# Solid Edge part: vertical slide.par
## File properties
Author: Deepak Maini
Template: Normal.par
Last saved by: Robert a Rhodes jr
Revision: 19
Application: Solid Edge
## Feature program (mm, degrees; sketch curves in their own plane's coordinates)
sketch for "unnamed Protrusion 1" plane through (0, 0, 0) normal (0, 0, 1) x-axis (1, 0, 0)
  line (-50, 27.936) -> (50, 27.936)
  line (50, 27.936) -> (50, -8.064)
  arc centre (0, 78.5385) radius 100 from (-50, -8.064) to (50, -8.064) ccw
  line (-50, 27.936) -> (-50, -8.064)
extrude "unnamed Protrusion 1" add finite 240 symmetric
sketch for "unnamed Cutout 1" plane through (0, 27.936, 0) normal (0, 1, 0) x-axis (-1, 0, 0)
  arc centre (0, 3) radius 123 from (-50, -109.3788) to (50, -109.3788) ccw
extrude "unnamed Cutout 1" cut through along -normal
sketch for "unnamed Protrusion 2" plane through (0, -30.264, 0) normal (0, 1, 0) x-axis (-1, 0, 0)
extrude "unnamed Protrusion 2" add through along +normal
sketch for "unnamed Cutout 2" plane through (0, 3.2373, 120) normal (0, 0, 1) x-axis (1, 0, 0)
extrude "unnamed Cutout 2" cut through along -normal
sketch for "unnamed Protrusion 3" #1 plane through (0, 3.2373, 120) normal (0, 0, 1) x-axis (1, 0, 0)
  circle centre (0, 15.6987) radius 8
sketch for "unnamed Protrusion 3" #2 plane through (0, 3.2373, 120) normal (0, 0, 1) x-axis (1, 0, 0)
extrude "unnamed Protrusion 3" add finite 25 along -normal
sketch for "unnamed Cutout 3" plane through (0, 7.936, 0) normal (0, 1, 0) x-axis (0, 0, -1)
  line (-95, 15) -> (-95, -15)
  line (-95, -15) -> (134.0741, -15)
  line (134.0741, -15) -> (134.0741, 15)
  line (134.0741, 15) -> (-95, 15)
extrude "unnamed Cutout 3" cut finite 1.2 along -normal
sketch for "unnamed Cutout 4" #1 plane through (0, -30.264, -39.6894) normal (0, -1, 0) x-axis (0, 0, -1)
  circle centre (27.9268, 0) radius 10
sketch for "unnamed Cutout 4" #2 plane through (0, -30.264, -39.6894) normal (0, -1, 0) x-axis (0, 0, -1)
  circle centre (-60.0732, 0) radius 8
extrude "unnamed Cutout 4" cut through along -normal
sketch for "unnamed Hole 1" plane through (-50, -1.164, 5.3106) normal (-1, 0, 0) x-axis (0, -1, 0)
  hole centre (-16.1, 51.6894) bore radius 3
hole "unnamed Hole 1"
pattern "unnamed Pattern 1" of "unnamed Hole 1"
pattern "unnamed Pattern 2"
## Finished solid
Body 1: solid body, 27 faces, 66 edges, 34 vertices.
  Faces by surface: plane 16, cylinder 11
  Edges by curve: line 39, circle 20, ellipse 6, intersection 1
Bounding box of the edges (mm): 100.000 x 64.200 x 240.000, from (-50, -30.264, -120) to (50, 33.936, 120).
Cylindrical faces by radius (mm): R3 x4, R8 x2, R10 x1, R15 x1, R100 x1, R115 x1, R123 x1
Planar faces by outward normal: +x 3, +y 5, +z 1, -x 3, -y 1, -z 1, oblique 2
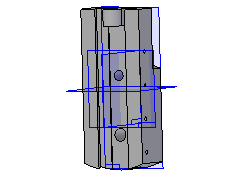
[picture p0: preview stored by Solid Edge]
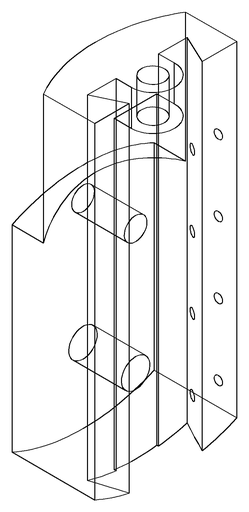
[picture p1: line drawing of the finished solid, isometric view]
